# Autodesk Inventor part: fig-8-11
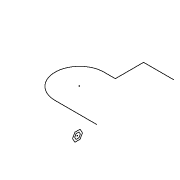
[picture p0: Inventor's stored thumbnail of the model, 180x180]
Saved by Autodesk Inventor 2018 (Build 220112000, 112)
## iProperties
Created: 2004-05
Part Number: fig-8-11
Document SubType Name: Modeling
Designer: CADCIM Technologies
Manufacturer: Standard
Standards Organization: Custom
Density: 1 g/cm^3
Material: Generic
Appearance: Default
Author: CADCIM Technologies
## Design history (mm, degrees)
sketch "Sketch1"
  geometry: L1 (-42.583, 3.219)-(-90.066, 3.219); L2 (-90.066, 58.92)-(-77.282, 58.92); L3 (-77.282, 58.92)-(-77.282, 91.063); L4 (-77.282, 91.063)-(-42.583, 91.063); A1 r 27.851 centre (-90.066, 31.07) between (-90.066, 58.92) and (-90.066, 3.219)
  constraints: 8 end point, 2 parallel, 2 point on circle, 2 tangent, 1 centre point, 1 perpendicular
workplane "Work Plane2"
sketch "Sketch2"
  geometry: L1 (16.303, 0)-(19.151, 4.934); L2 (19.151, 4.934)-(24.849, 4.934); L3 (24.849, 4.934)-(27.697, 0); L4 (27.697, 0)-(24.849, -4.934); L5 (24.849, -4.934)-(19.151, -4.934); L6 (19.151, -4.934)-(16.303, 0); L7 (18.744, 0)-(20.372, 2.819); L8 (20.372, 2.819)-(23.628, 2.819); L9 (23.628, 2.819)-(25.256, 0); L10 (25.256, 0)-(23.628, -2.819); L11 (23.628, -2.819)-(20.372, -2.819); L12 (20.372, -2.819)-(18.744, 0); 2 further points
  constraints: 24 end point, 1 coincident, 22 other
